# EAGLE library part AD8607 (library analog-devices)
Precision Micropower, Low Noise CMOS, Rail-to-Rail Input/Output Operational Amplifiers Source: http://www.analog.com/static/imported-files/data_sheets/AD8603_8607_8609.pdf
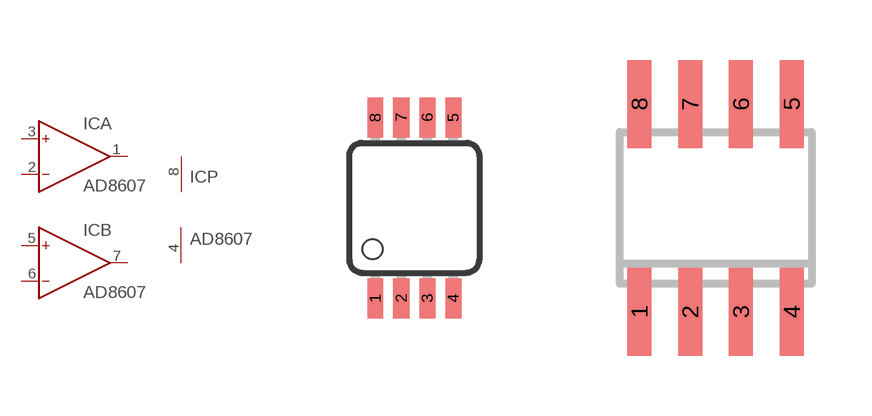
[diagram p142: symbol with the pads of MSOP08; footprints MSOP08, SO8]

Designator prefix IC; gates A=OP B=OP P=PWR+-

## AD8607RM (MF: ALTERA CORPORATION; MPN: AD8607ARMZ-REEL; OC_FARNELL: 1464990; OC_NEWARK: 59K6925)  [MSOP08]
1  A:OUT  out
2  A:IN-  in
3  A:IN+  in
4  P:V-  pwr
5  B:IN+  in
6  B:IN-  in
7  B:OUT  out
8  P:V+  pwr

## AD8607R (MPN: AD8607ARMZ-R2; OC_FARNELL: 1651293; OC_NEWARK: 19M8927)  [SO8]
Pads as for MSOP08

## Footprint MSOP08 (pad centres in mm)
8-Lead micro SO (RM-8) Source: http://www.analog.com/UploadedFiles/Data_Sheets/703465986AD8611_2_0.pdf
smd 0.4 x 1: 1 -0.976,-2.263; 2 -0.326,-2.263; 3 0.324,-2.263; 4 0.974,-2.263; 5 0.974,2.262; 6 0.324,2.262; 7 -0.326,2.262; 8 -0.976,2.262

## Footprint SO8 (pad centres in mm)
8-Lead Small Outline IC (SO-8) Source: http://www.analog.com/UploadedFiles/Data_Sheets/703465986AD8611_2_0.pdf
smd 0.6 x 2.2: 1 -1.905,-2.6; 2 -0.635,-2.6; 3 0.635,-2.6; 4 1.905,-2.6; 5 1.905,2.6; 6 0.635,2.6; 7 -0.635,2.6; 8 -1.905,2.6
